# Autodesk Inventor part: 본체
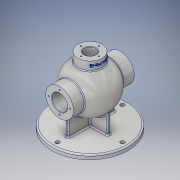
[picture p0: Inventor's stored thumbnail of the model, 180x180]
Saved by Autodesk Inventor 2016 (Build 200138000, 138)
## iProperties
Created: 2020-08
Part Number: 본체
Material: 알루미늄 6061
Document SubType Name: Modeling
Designer: Administrator
Density: 2.7 g/cm^3
Appearance: 알루미늄 - 평지
Mass: 1752.69 g
Surface Area: 1342.58 cm^2
Volume: 649.145 cm^3
Author: Administrator
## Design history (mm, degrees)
sketch "스케치1"
  geometry: L1 (-68, 31)-(68, 31); L2 (68, 31)-(68, 0); L3 (68, 0)-(-68, 0); L4 (-68, 0)-(-68, 31); 2 further points
  constraints: 8 end point, 2 parallel, 1 coincident, 1 horizontal, 1 midpoint, 1 perpendicular
  dimensions: "d0" = 31 distance of L3.end L1.start; "d1" = 136 distance of L1.start L1.end
revolve "회전1" sketch "스케치1" stored, may be unused: angle "d2" = 90 deg
node "작업 평면1"
sketch "스케치2"
  geometry: C1 r 85 at (0, 0); 1 further point
  constraints: 1 centre point, 1 coincident
  dimensions: "d4" = 170 diameter of C1
extrude "돌출1" join sketch "스케치2" distance "d5" = 10; taper "d6" = 0 deg
sketch "스케치3"
  geometry: L1 (-53, 0)-(53, 0); A1 r 53 centre (0, 0) between (53, 0) and (-53, 0); 2 further points
  constraints: 2 coincident, 2 end point, 2 point on circle, 1 centre point, 1 horizontal, 1 midpoint
  dimensions: "d7" = 53 radius of A1
revolve "회전2" sketch "스케치3" stored, may be unused: angle "d8" = 90 deg
sketch "스케치4"
  geometry: L1 (-52, 1)-(52, 1); L2 (52, 1)-(52, -75); L3 (52, -75)-(-52, -75); L4 (-52, -75)-(-52, 1); L5 (85, -75)-(-85, -75) reference; 2 further points
  constraints: 8 end point, 2 midpoint, 2 parallel, 1 horizontal, 1 perpendicular
  dimensions: "d9" = 104 distance of L1.start L1.end; "d10" = 76 distance of L3.end L1.start
extrude "돌출2" join sketch "스케치4" stored distance "d11" = 8; taper "d12" = 0 deg
sketch "스케치5"
  geometry: L1 (85, -75)-(-85, -75) reference; L2 (43, 10)-(-43, 10); L3 (-43, 10)-(-43, -75); L4 (-43, -75)-(43, -75); L5 (43, -75)-(43, 10); 2 further points
  constraints: 8 end point, 2 midpoint, 2 parallel, 1 horizontal, 1 perpendicular
  dimensions: "d13" = 85 distance of L4.end L2.start; "d14" = 86 distance of L3.end L4.end
extrude "돌출3" join sketch "스케치5" stored distance "d15" = 8; taper "d16" = 0 deg
hole "구멍1" diameter "d19" = 35; stored, may be unused: countersink angle "d23" = 90 deg, drill point angle "d25" = 0 deg; dims "d17" = 10, "d18" = 10, "d20" = 6, "d21" = 4, "d22" = 2, "d24" = 8
node "작업 평면3"
sketch "스케치7"
  geometry: C1 r 27 at (0, 0); 1 further point
  constraints: 1 centre point, 1 coincident
  dimensions: "d31" = 54 diameter of C1
extrude "돌출5" join sketch "스케치7" stored distance "d32" = 1.75; taper "d33" = 0 deg
hole "구멍2" diameter "d36" = 26; stored, may be unused: countersink angle "d40" = 90 deg, drill point angle "d42" = 0 deg; dims "d34" = 10, "d35" = 10, "d37" = 6, "d38" = 4, "d39" = 2, "d41" = 65
sketch "스케치8"
  geometry: L1 (0, 0)-(0, 24)
  constraints: 2 end point, 1 vertical
  dimensions: "d43" = 24 distance of L1.start L1.end
hole "구멍3" sketch "스케치8" at (0, 24) diameter "d44" = 3.242; stored, may be unused: countersink angle "d48" = 90 deg, drill point angle "d50" = 118 deg; dims "d45" = 12, "d46" = 4, "d47" = 2, "d49" = 15
sketch "스케치9"
  geometry: L1 (0, 0)-(0, 20)
  constraints: 2 end point, 1 vertical
  dimensions: "d54" = 20 distance of L1.start L1.end
hole "구멍4" sketch "스케치9" at (0, 20) diameter "d55" = 3.242; stored, may be unused: countersink angle "d59" = 90 deg, drill point angle "d61" = 118 deg; dims "d56" = 12, "d57" = 4, "d58" = 2, "d60" = 15
sketch "스케치10"
  geometry: L1 (0, 0)-(0, 72.5)
  constraints: 2 end point, 1 vertical
  dimensions: "d65" = 72.5 distance of L1.start L1.end
hole "구멍5" sketch "스케치10" at (0, 72.5) diameter "d66" = 9; stored, may be unused: countersink angle "d70" = 90 deg, drill point angle "d72" = 0 deg; dims "d67" = 12, "d68" = 4, "d69" = 2, "d71" = 15
chamfer "모따기1" distance "d76" = 1; stored, may be unused: second distance "d77" = 2, angle "d78" = 45 deg
fillet "모깎기1" dims "d79" = 3
fillet "모깎기2" dims "d80" = 3
fillet "모깎기3" dims "d81" = 3
node "작업 평면4"
sketch "스케치11"
  geometry: L1 (-27, 65)-(27, 65) reference; L2 (-27, 65)-(0, 65); L3 (0, 65)-(0, 56); 2 further points
  constraints: 4 end point, 1 coincident, 1 midpoint, 1 vertical, 1 other
  dimensions: "d83" = 27 distance of L2.end L1.start; "d84" = 9 distance of L2.end L3.end
feature "엠보싱1" sketch "스케치11" dims "d0" = 31, "d1" = 136, "d9" = 104, "d10" = 76, "d85" = 0.5, "d86" = 0
sketch "스케치12"
  geometry: L1 (43, 0)-(-43, 0); A1 r 43 centre (0, 0) between (43, 0) and (-43, 0); 2 further points
  constraints: 2 coincident, 2 end point, 2 point on circle, 1 centre point, 1 horizontal, 1 midpoint
  dimensions: "d88" = 43 radius of A1
revolve "회전3" sketch "스케치12" stored, may be unused: angle "d89" = 90 deg
node "작업 평면5"
sketch "스케치13"
  geometry: C1 r 18.5 at (0, 0); 1 further point
  constraints: 1 centre point, 1 coincident
  dimensions: "d91" = 37 diameter of C1
extrude "돌출6" cut sketch "스케치13" distance "d92" = 1.75; taper "d93" = 0 deg
node "솔리드1"
pattern_circular "원형 패턴1" dims angle "d52" = 360 deg
mirror "대칭1"
pattern_circular "원형 패턴2" dims angle "d63" = 360 deg
pattern_circular "원형 패턴3" dims angle "d74" = 360 deg
other parameters: "d3" = -85, "d30" = 65, "d82" = 27, "d90" = -16
